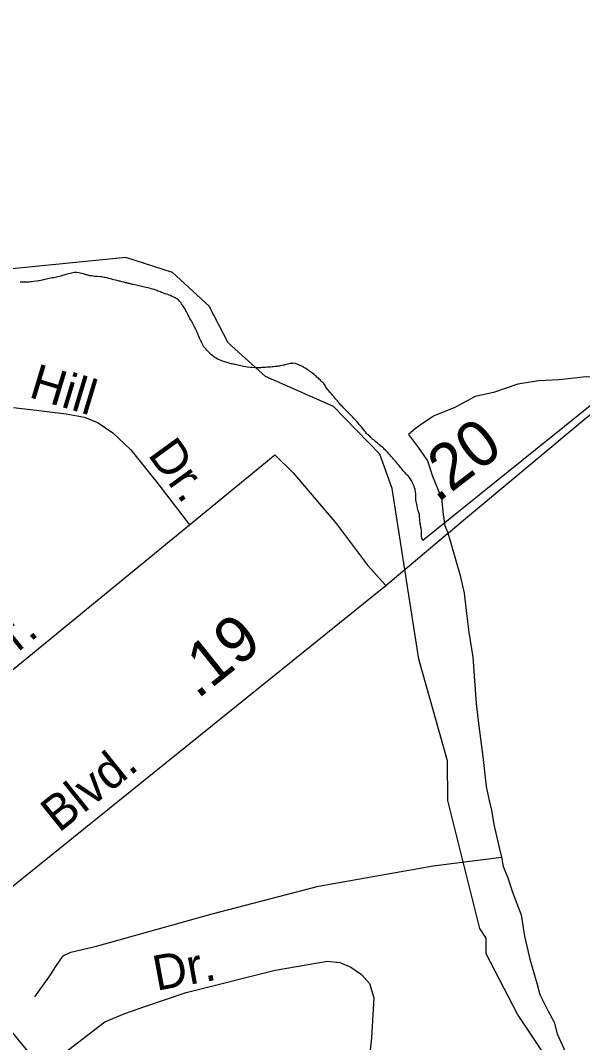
# Model space of a CAD drawing. Extents: x 2315291 to 2336543, y 597177 to 615230.
# Drawn here: x 2323766 to 2325292, y 599288 to 602063 of the extents above; entities that cross this region are included whole.
import ezdxf

# ---------------------------------------------------------------- set-up
doc = ezdxf.new("R2010")
doc.units = 0
for name, color, linetype in [('Exist Boundary Political City Limit New', 7, 'Continuous'), ('Exist Hydrographic Creek Single Shore', 7, 'Continuous'), ('Exist Hydrographic Misc Water Feature', 7, 'Continuous'), ('Exist Road Non-System Type 51', 7, 'Continuous'), ('Exist Road Non-System Type 51 Label', 7, 'Continuous'), ('Exist Road Primary US Attributed', 7, 'Continuous'), ('Exist Road Primary US Label', 7, 'Continuous'), ('Exist Road Primary US Mileage Tenths English Label', 7, 'Continuous'), ('Map Preparation Boundary City Limit Buffer Line', 7, 'Continuous')]:
    doc.layers.add(name, color=color, linetype=linetype)

msp = doc.modelspace()

# ---------------------------------------------------------------- linework, layer by layer
at = {"layer": 'Exist Boundary Political City Limit New'}
for points in [[(2324159, 601321.2), (2324156, 601322.1), (2324152.2, 601323.5), (2324148.5, 601324.9), (2324145.8, 601326.1), (2324142.2, 601327.5), (2324139.2, 601328.7), (2324135.8, 601330.1), (2324132, 601331.6), (2324128.8, 601332.7), (2324124.2, 601333.9), (2324120.5, 601335), (2324116.5, 601336.1), (2324111.2, 601337.4), (2324106.8, 601338.4), (2324103, 601339.3), (2324099, 601340.2), (2324095.5, 601341), (2324091.2, 601341.9), (2324087.2, 601342.8), (2324083.5, 601343.6), (2324080, 601344.4), (2324076, 601345.2), (2324071.8, 601346.3), (2324068.8, 601347), (2324066, 601347.7), (2324062, 601348.7), (2324058.5, 601349.5), (2324054.2, 601350.6), (2324051.2, 601351.3), (2324047.5, 601352.3), (2324041.5, 601353.8), (2324036.8, 601355), (2324034, 601355.8), (2324031, 601356.5), (2324028, 601357.2), (2324024, 601358.2), (2324019.2, 601359.4), (2324016.5, 601360.2), (2324013.5, 601361), (2324009.8, 601362), (2324006.2, 601362.9), (2324003, 601363.7), (2324000, 601364.4), (2323996, 601365.2), (2323993.2, 601365.8), (2323989.2, 601366.5), (2323986.2, 601366.8), (2323982.2, 601367.2), (2323974.2, 601367.7), (2323970.8, 601367.9), (2323966.2, 601368.5), (2323962.2, 601369), (2323958.5, 601369.6), (2323953.8, 601370.3), (2323949, 601371.4), (2323946.2, 601372.2), (2323943.2, 601373), (2323939.5, 601374.1), (2323936.5, 601375.1), (2323931.8, 601376.4), (2323928, 601377.4), (2323924, 601378.3), (2323919.2, 601379.2), (2323916.2, 601379), (2323912.2, 601378.5), (2323908.2, 601377.9), (2323904.2, 601377.2), (2323901, 601376.6), (2323896.5, 601375.4), (2323892.8, 601374.4), (2323888.8, 601373.3), (2323883.5, 601371.8), (2323879.2, 601370.6), (2323875.2, 601369.4), (2323871.5, 601368.4), (2323867, 601367.1), (2323863.8, 601366.4), (2323859.8, 601365.7), (2323856, 601364.9), (2323852, 601364.2), (2323848.5, 601363.6), (2323844, 601362.6), (2323840.2, 601361.6), (2323836.2, 601360.8), (2323831.5, 601359.6), (2323828.5, 601358.9), (2323824.5, 601358.1), (2323820.8, 601357.2), (2323816.8, 601356.4), (2323813.5, 601355.9), (2323810, 601355.3), (2323801, 601354.2), (2323796.2, 601353.6), (2323793, 601353.4), (2323789, 601353.1), (2323785, 601352.9)], [(2323785, 601352.9), (2323780.5, 601352.6), (2323777.5, 601352.5), (2323773, 601352.7), (2323769.5, 601352.6), (2323768, 601352.8), (2323765, 601353)], [(2324449.2, 601122.7), (2324444.8, 601122.2), (2324441.2, 601121.9), (2324438.2, 601121.8), (2324435.2, 601121.5), (2324431.2, 601121.2), (2324427, 601120.9), (2324424, 601120.8), (2324420.2, 601120.6), (2324417.2, 601120.4), (2324413.2, 601120.2), (2324408.2, 601120.1), (2324405.2, 601120.2), (2324393.2, 601120.9), (2324390.2, 601121.2), (2324381.2, 601122.3), (2324377.5, 601122.8), (2324372.2, 601123.4), (2324367.5, 601124.4), (2324363.8, 601125.4), (2324359.8, 601126.4), (2324355.8, 601127.6), (2324350, 601128.8), (2324347.2, 601129.4), (2324344.2, 601130.1), (2324340.5, 601130.8), (2324337.5, 601131.4), (2324334.5, 601132.2), (2324329.8, 601133.6), (2324326.8, 601134.5), (2324323, 601135.6), (2324319.5, 601136.7), (2324315.2, 601138.1), (2324311.5, 601139.3), (2324307.8, 601140.7), (2324303.5, 601142.4), (2324300.5, 601144), (2324297.2, 601146.1), (2324293.8, 601148.2), (2324290.5, 601150.4), (2324287.8, 601152.3), (2324284.5, 601155.6), (2324281.5, 601158.3), (2324279.2, 601160.4), (2324277, 601162.7), (2324274.2, 601165.6), (2324271.8, 601168.4), (2324269, 601171.3), (2324266.2, 601174.3), (2324263.2, 601178), (2324261.8, 601180.8), (2324260, 601184.4), (2324258.2, 601187.9), (2324257, 601190.7), (2324255.5, 601193.8), (2324254, 601197.1), (2324252.2, 601200.7), (2324251.2, 601203.4), (2324250, 601206.2), (2324248.2, 601209.9), (2324247, 601212.8), (2324245.2, 601217.2), (2324243.5, 601220.9), (2324242.2, 601224), (2324241, 601226.8), (2324239.2, 601230), (2324236.8, 601235.2), (2324234.8, 601238.8), (2324232.2, 601243.8), (2324230, 601247.5), (2324227.8, 601250.9), (2324226, 601254.4), (2324224.2, 601258), (2324222.8, 601260.8), (2324220.5, 601265.1), (2324218.5, 601268.6), (2324216.8, 601272.1), (2324215, 601275.2), (2324212.8, 601279.1), (2324210.8, 601282.5), (2324208.2, 601286.6), (2324205.8, 601290.7), (2324203.2, 601294.3), (2324200.8, 601297.4), (2324198.2, 601300.5), (2324194.8, 601304.3), (2324190.2, 601307.5), (2324189, 601308.7), (2324185.8, 601310), (2324182.2, 601311.9), (2324178, 601314.1), (2324175.8, 601314.9), (2324173, 601316.1), (2324169.2, 601317.5), (2324165.5, 601319), (2324162.8, 601320), (2324159, 601321.2)], [(2325664.2, 601300), (2324858.5, 600651.2), (2324857, 600654.8), (2324855.5, 600657.3), (2324855, 600661), (2324854.2, 600665.4), (2324854.5, 600668.9), (2324854.5, 600672.9), (2324854.8, 600676.9), (2324854.8, 600680.1), (2324854, 600683.8), (2324853.2, 600686.8), (2324852.8, 600689.7), (2324851.8, 600693.6), (2324851.2, 600696.5), (2324850.8, 600700.5), (2324850.5, 600704), (2324850, 600706.9), (2324849.8, 600710.4), (2324849.5, 600713.6), (2324849, 600718.4), (2324848.8, 600721.8), (2324847.5, 600726.2), (2324846.5, 600729), (2324845.5, 600732), (2324844.5, 600735.5), (2324843.8, 600739.6), (2324843.2, 600742.6), (2324842.5, 600745.6), (2324842, 600749), (2324841, 600753.4), (2324840.2, 600757.3), (2324839.5, 600761.8), (2324839.2, 600765.2), (2324839, 600769.2), (2324839, 600773.2), (2324838.8, 600778), (2324838.2, 600783.2), (2324837.8, 600787.1), (2324837, 600790.2), (2324835.8, 600794.8), (2324834.5, 600798.6), (2324832.2, 600804.2), (2324830.5, 600807.9), (2324828.8, 600811.4), (2324826.8, 600815.4), (2324823.8, 600820), (2324821.2, 600823.2), (2324818.5, 600826.6), (2324816, 600829.1), (2324813.2, 600831.9), (2324810.2, 600834.7), (2324807.2, 600837.6), (2324805.2, 600840.1), (2324803, 600843.2), (2324800.5, 600846.4), (2324797.8, 600850), (2324795.8, 600852.4), (2324793, 600855.8), (2324790.5, 600858.8), (2324787.8, 600861.9), (2324784.8, 600865.4), (2324781.8, 600868.8), (2324778.5, 600872.4), (2324776, 600875.4), (2324773.2, 600878.4), (2324771.5, 600880.6), (2324769.5, 600882.9), (2324766, 600886.8), (2324762.8, 600890.4), (2324759.8, 600893.9), (2324757.2, 600896.2), (2324754.5, 600898.8), (2324752.5, 600900.8)], [(2324461.8, 601124.1), (2324457.2, 601123.5), (2324453.2, 601123.1), (2324449.2, 601122.7)], [(2324752.5, 600900.8), (2324750.2, 600902.8), (2324746.8, 600906.1), (2324743.5, 600908.8), (2324741.2, 600910.7), (2324738, 600913.2), (2324735, 600915.7), (2324731.8, 600918.2), (2324728.8, 600920.8), (2324725.8, 600923.4), (2324722.8, 600926), (2324719.2, 600929), (2324716.8, 600931.4), (2324714, 600934.2), (2324711, 600936.9), (2324708, 600939.4), (2324705.5, 600942), (2324702.2, 600946.5), (2324700.2, 600948.7), (2324697.8, 600951.8), (2324694.5, 600955.9), (2324691.5, 600959.6), (2324689, 600962.6), (2324686.2, 600965.6), (2324683.2, 600969.2), (2324679.8, 600973.1), (2324677, 600976.1), (2324674.2, 600979.1), (2324671.2, 600982.4), (2324668.8, 600985.2), (2324666.2, 600987.9), (2324664.2, 600990.1), (2324661.5, 600992.9), (2324658.5, 600996.1), (2324654.8, 600999.7), (2324652.2, 601002.2), (2324649.5, 601005), (2324646, 601008.4), (2324643, 601011.4), (2324639.8, 601015.1), (2324635.8, 601019.2), (2324633.2, 601022.1), (2324631.2, 601024.3), (2324629, 601027), (2324626.5, 601030.1), (2324624, 601033.2), (2324621.5, 601036.1), (2324618.8, 601039.3), (2324616.2, 601042.4), (2324614.2, 601044.7), (2324612.2, 601046.9), (2324610, 601049.6), (2324606, 601054), (2324603, 601057.5), (2324600.5, 601060.5), (2324598.5, 601062.8), (2324596, 601067), (2324594.2, 601069.6), (2324592.8, 601072.2), (2324591.2, 601074.8), (2324589.2, 601077.7), (2324587, 601080), (2324584.2, 601081.9), (2324582.5, 601084.2), (2324579.5, 601087.1), (2324576, 601090.6), (2324573.8, 601092.6), (2324570.8, 601095.2), (2324568.5, 601097.2), (2324566.2, 601099.2), (2324562.8, 601102.3), (2324559.2, 601104.9), (2324557, 601106.7), (2324553.8, 601109.1), (2324550.5, 601111.4), (2324547.5, 601113.5), (2324544, 601115.9), (2324541.5, 601117.6), (2324539, 601119.2), (2324535.5, 601121.4), (2324533, 601123.1), (2324527.8, 601125.6), (2324524.8, 601126.8), (2324521.2, 601128.4), (2324516.8, 601130.4), (2324514, 601131), (2324510, 601133), (2324505.8, 601132.2), (2324502.2, 601131.7), (2324497.8, 601131.5), (2324494.5, 601130.7), (2324490.5, 601129.8), (2324486.8, 601128.8), (2324482.8, 601127.8), (2324479.5, 601127), (2324475, 601126.2), (2324471, 601125.5), (2324468, 601125), (2324465, 601124.6), (2324461.8, 601124.1)]]:
    msp.add_lwpolyline(points, dxfattribs=at)
at = {"layer": 'Exist Hydrographic Creek Single Shore'}
msp.add_lwpolyline([(2325385.4, 599067.9), (2325242.4, 599173.7), (2325115.3, 599365.4), (2325030.4, 599529.4), (2325030.4, 599572), (2325013.4, 599597.6), (2324926.5, 599945.2), (2324925.4, 600053.4), (2324847.3, 600329.2), (2324775.3, 600792.3), (2324741.3, 600886.1), (2324615.4, 601015.5), (2324431.3, 601096.7), (2324329.3, 601187.7), (2324278.3, 601287.4), (2324178.4, 601378.5), (2324052.3, 601419.4), (2323661.3, 601380.6), (2323452.3, 601444.4), (2323301.4, 601520.3), (2323108.3, 601692.9), (2322948.3, 601906.3), (2322863.2, 602047.3), (2322862.4, 602080.1)], dxfattribs=at)
at = {"layer": 'Exist Hydrographic Misc Water Feature'}
for points in [[(2326560.3, 600813.6), (2326414.1, 600842), (2326229.1, 600925.8), (2326060.4, 600999.9), (2325711.8, 601048.3), (2325569.9, 601070.9), (2325449.3, 601087.4), (2325387.4, 601091), (2325301.7, 601095.8), (2325227.9, 601087.1), (2325171.9, 601084.6), (2325115.9, 601075.9), (2325050.1, 601053.4), (2325000.3, 601042.6), (2324944.7, 601012.1), (2324889.1, 600989.6), (2324857.1, 600969.3), (2324837.5, 600954.8), (2324819.4, 600938.9)], [(2324819.4, 600938.9), (2324846.3, 600903.2), (2324870.5, 600867.5), (2324884.8, 600825.6), (2324909.2, 600766), (2324913.7, 600721.9), (2324918.3, 600692), (2324926.5, 600672.1), (2324959.9, 600556.4), (2324970.1, 600508.6), (2324977.1, 600452.8), (2324983.5, 600402.8), (2324993.9, 600335.1), (2325003.1, 600209.2), (2325010.3, 600147.3), (2325021, 600065.4), (2325029.8, 599983.4), (2325038.4, 599945.6), (2325044.4, 599919.6), (2325050.9, 599880.1), (2325065.7, 599818.2), (2325071.8, 599792.1)], [(2323804.8, 599412.7), (2323844, 599467.2), (2323863.9, 599497.4), (2323881.5, 599523.6), (2323903, 599533.7), (2323972.6, 599550.4), (2324285.9, 599637.9), (2324574.6, 599712.9), (2324886.1, 599768.2), (2325071.8, 599792.1)], [(2325071.8, 599792.1), (2325076.1, 599766.4), (2325088.4, 599738.1), (2325101.2, 599696.5), (2325125.1, 599634.9), (2325134.2, 599576.8), (2325148.7, 599515), (2325167.4, 599449.3), (2325175.6, 599419.3), (2325198.1, 599373.7), (2325214.6, 599344.1), (2325222.8, 599312), (2325245.1, 599262.4), (2325257.6, 599232.5), (2325274, 599208.6), (2325282.2, 599186.6)]]:
    msp.add_lwpolyline(points, dxfattribs=at)
at = {"layer": 'Exist Road Non-System Type 51'}
for p, q in [((2323434.4, 600047.1), (2324225.1, 600694.3)), ((2323552, 599546.7), (2323826.4, 599215.3))]:
    msp.add_line(p, q, dxfattribs=at)
for points in [[(2323746.6, 601012.2), (2323815.5, 601004.7), (2323889.9, 600995.3), (2323939.9, 600985.8), (2323976.4, 600970.9), (2324016.9, 600943.9), (2324065.6, 600897.2), (2324141.3, 600802.5), (2324225.1, 600694.3)], [(2324225.1, 600694.3), (2324456.3, 600883.7), (2324506.3, 600835), (2324623.9, 600697), (2324707.7, 600584.8), (2324757.7, 600529.3)], [(2323826.4, 599215.3), (2323995.3, 599344.4), (2324049.4, 599367.4), (2324103.5, 599386.4), (2324215.7, 599424.2), (2324457.6, 599485.1), (2324599.5, 599509.5), (2324633.3, 599505.4), (2324663.1, 599493.2), (2324691.5, 599472.9), (2324713.1, 599448.6), (2324725.3, 599409.4), (2324718.5, 599301.2), (2324713.1, 599251.1), (2324702.7, 599170.3), (2324701, 599128.4), (2324709.5, 599090.5), (2324728, 599066.5), (2324739.4, 599053.4), (2324759, 599035.4), (2324778, 599017.1)]]:
    msp.add_lwpolyline(points, dxfattribs=at)
at = {"layer": 'Exist Road Primary US Attributed'}
msp.add_lwpolyline([(2321872.6, 598168.2), (2322100.6, 598357.7), (2322368.8, 598574.3), (2322589.4, 598759.9), (2322822.5, 598950.5), (2322989.6, 599086.8), (2323103.2, 599177.4), (2323552, 599546.7), (2323723.6, 599695.4), (2324757.7, 600529.3), (2324925.6, 600670.6), (2324932.1, 600676), (2324968.9, 600707), (2325301.4, 600984), (2325554.9, 601184.8), (2325709, 601298.4), (2326037.4, 601569.3), (2326353.8, 601821.9), (2326377, 601842), (2326507.1, 601954.4)], dxfattribs=at)
at = {"layer": 'Map Preparation Boundary City Limit Buffer Line'}
for points in [[(2324159, 601321.2), (2324156, 601322.1), (2324152.2, 601323.5), (2324148.5, 601324.9), (2324145.8, 601326.1), (2324142.2, 601327.5), (2324139.2, 601328.7), (2324135.8, 601330.1), (2324132, 601331.6), (2324128.8, 601332.7), (2324124.2, 601333.9), (2324120.5, 601335), (2324116.5, 601336.1), (2324111.2, 601337.4), (2324106.8, 601338.4), (2324103, 601339.3), (2324099, 601340.2), (2324095.5, 601341), (2324091.2, 601341.9), (2324087.2, 601342.8), (2324083.5, 601343.6), (2324080, 601344.4), (2324076, 601345.2), (2324071.8, 601346.3), (2324068.8, 601347), (2324066, 601347.7), (2324062, 601348.7), (2324058.5, 601349.5), (2324054.2, 601350.6), (2324051.2, 601351.3), (2324047.5, 601352.3), (2324041.5, 601353.8), (2324036.8, 601355), (2324034, 601355.8), (2324031, 601356.5), (2324028, 601357.2), (2324024, 601358.2), (2324019.2, 601359.4), (2324016.5, 601360.2), (2324013.5, 601361), (2324009.8, 601362), (2324006.2, 601362.9), (2324003, 601363.7), (2324000, 601364.4), (2323996, 601365.2), (2323993.2, 601365.8), (2323989.2, 601366.5), (2323986.2, 601366.8), (2323982.2, 601367.2), (2323974.2, 601367.7), (2323970.8, 601367.9), (2323966.2, 601368.5), (2323962.2, 601369), (2323958.5, 601369.6), (2323953.8, 601370.3), (2323949, 601371.4), (2323946.2, 601372.2), (2323943.2, 601373), (2323939.5, 601374.1), (2323936.5, 601375.1), (2323931.8, 601376.4), (2323928, 601377.4), (2323924, 601378.3), (2323919.2, 601379.2), (2323916.2, 601379), (2323912.2, 601378.5), (2323908.2, 601377.9), (2323904.2, 601377.2), (2323901, 601376.6), (2323896.5, 601375.4), (2323892.8, 601374.4), (2323888.8, 601373.3), (2323883.5, 601371.8), (2323879.2, 601370.6), (2323875.2, 601369.4), (2323871.5, 601368.4), (2323867, 601367.1), (2323863.8, 601366.4), (2323859.8, 601365.7), (2323856, 601364.9), (2323852, 601364.2), (2323848.5, 601363.6), (2323844, 601362.6), (2323840.2, 601361.6), (2323836.2, 601360.8), (2323831.5, 601359.6), (2323828.5, 601358.9), (2323824.5, 601358.1), (2323820.8, 601357.2), (2323816.8, 601356.4), (2323813.5, 601355.9), (2323810, 601355.3), (2323801, 601354.2), (2323796.2, 601353.6), (2323793, 601353.4), (2323789, 601353.1), (2323785, 601352.9)], [(2323785, 601352.9), (2323780.5, 601352.6), (2323777.5, 601352.5), (2323773, 601352.7), (2323769.5, 601352.6), (2323768, 601352.8), (2323765, 601353)], [(2324449.2, 601122.7), (2324444.8, 601122.2), (2324441.2, 601121.9), (2324438.2, 601121.8), (2324435.2, 601121.5), (2324431.2, 601121.2), (2324427, 601120.9), (2324424, 601120.8), (2324420.2, 601120.6), (2324417.2, 601120.4), (2324413.2, 601120.2), (2324408.2, 601120.1), (2324405.2, 601120.2), (2324393.2, 601120.9), (2324390.2, 601121.2), (2324381.2, 601122.3), (2324377.5, 601122.8), (2324372.2, 601123.4), (2324367.5, 601124.4), (2324363.8, 601125.4), (2324359.8, 601126.4), (2324355.8, 601127.6), (2324350, 601128.8), (2324347.2, 601129.4), (2324344.2, 601130.1), (2324340.5, 601130.8), (2324337.5, 601131.4), (2324334.5, 601132.2), (2324329.8, 601133.6), (2324326.8, 601134.5), (2324323, 601135.6), (2324319.5, 601136.7), (2324315.2, 601138.1), (2324311.5, 601139.3), (2324307.8, 601140.7), (2324303.5, 601142.4), (2324300.5, 601144), (2324297.2, 601146.1), (2324293.8, 601148.2), (2324290.5, 601150.4), (2324287.8, 601152.3), (2324284.5, 601155.6), (2324281.5, 601158.3), (2324279.2, 601160.4), (2324277, 601162.7), (2324274.2, 601165.6), (2324271.8, 601168.4), (2324269, 601171.3), (2324266.2, 601174.3), (2324263.2, 601178), (2324261.8, 601180.8), (2324260, 601184.4), (2324258.2, 601187.9), (2324257, 601190.7), (2324255.5, 601193.8), (2324254, 601197.1), (2324252.2, 601200.7), (2324251.2, 601203.4), (2324250, 601206.2), (2324248.2, 601209.9), (2324247, 601212.8), (2324245.2, 601217.2), (2324243.5, 601220.9), (2324242.2, 601224), (2324241, 601226.8), (2324239.2, 601230), (2324236.8, 601235.2), (2324234.8, 601238.8), (2324232.2, 601243.8), (2324230, 601247.5), (2324227.8, 601250.9), (2324226, 601254.4), (2324224.2, 601258), (2324222.8, 601260.8), (2324220.5, 601265.1), (2324218.5, 601268.6), (2324216.8, 601272.1), (2324215, 601275.2), (2324212.8, 601279.1), (2324210.8, 601282.5), (2324208.2, 601286.6), (2324205.8, 601290.7), (2324203.2, 601294.3), (2324200.8, 601297.4), (2324198.2, 601300.5), (2324194.8, 601304.3), (2324190.2, 601307.5), (2324189, 601308.7), (2324185.8, 601310), (2324182.2, 601311.9), (2324178, 601314.1), (2324175.8, 601314.9), (2324173, 601316.1), (2324169.2, 601317.5), (2324165.5, 601319), (2324162.8, 601320), (2324159, 601321.2)], [(2325664.2, 601300), (2324858.5, 600651.2), (2324857, 600654.8), (2324855.5, 600657.3), (2324855, 600661), (2324854.2, 600665.4), (2324854.5, 600668.9), (2324854.5, 600672.9), (2324854.8, 600676.9), (2324854.8, 600680.1), (2324854, 600683.8), (2324853.2, 600686.8), (2324852.8, 600689.7), (2324851.8, 600693.6), (2324851.2, 600696.5), (2324850.8, 600700.5), (2324850.5, 600704), (2324850, 600706.9), (2324849.8, 600710.4), (2324849.5, 600713.6), (2324849, 600718.4), (2324848.8, 600721.8), (2324847.5, 600726.2), (2324846.5, 600729), (2324845.5, 600732), (2324844.5, 600735.5), (2324843.8, 600739.6), (2324843.2, 600742.6), (2324842.5, 600745.6), (2324842, 600749), (2324841, 600753.4), (2324840.2, 600757.3), (2324839.5, 600761.8), (2324839.2, 600765.2), (2324839, 600769.2), (2324839, 600773.2), (2324838.8, 600778), (2324838.2, 600783.2), (2324837.8, 600787.1), (2324837, 600790.2), (2324835.8, 600794.8), (2324834.5, 600798.6), (2324832.2, 600804.2), (2324830.5, 600807.9), (2324828.8, 600811.4), (2324826.8, 600815.4), (2324823.8, 600820), (2324821.2, 600823.2), (2324818.5, 600826.6), (2324816, 600829.1), (2324813.2, 600831.9), (2324810.2, 600834.7), (2324807.2, 600837.6), (2324805.2, 600840.1), (2324803, 600843.2), (2324800.5, 600846.4), (2324797.8, 600850), (2324795.8, 600852.4), (2324793, 600855.8), (2324790.5, 600858.8), (2324787.8, 600861.9), (2324784.8, 600865.4), (2324781.8, 600868.8), (2324778.5, 600872.4), (2324776, 600875.4), (2324773.2, 600878.4), (2324771.5, 600880.6), (2324769.5, 600882.9), (2324766, 600886.8), (2324762.8, 600890.4), (2324759.8, 600893.9), (2324757.2, 600896.2), (2324754.5, 600898.8), (2324752.5, 600900.8)], [(2324461.8, 601124.1), (2324457.2, 601123.5), (2324453.2, 601123.1), (2324449.2, 601122.7)], [(2324752.5, 600900.8), (2324750.2, 600902.8), (2324746.8, 600906.1), (2324743.5, 600908.8), (2324741.2, 600910.7), (2324738, 600913.2), (2324735, 600915.7), (2324731.8, 600918.2), (2324728.8, 600920.8), (2324725.8, 600923.4), (2324722.8, 600926), (2324719.2, 600929), (2324716.8, 600931.4), (2324714, 600934.2), (2324711, 600936.9), (2324708, 600939.4), (2324705.5, 600942), (2324702.2, 600946.5), (2324700.2, 600948.7), (2324697.8, 600951.8), (2324694.5, 600955.9), (2324691.5, 600959.6), (2324689, 600962.6), (2324686.2, 600965.6), (2324683.2, 600969.2), (2324679.8, 600973.1), (2324677, 600976.1), (2324674.2, 600979.1), (2324671.2, 600982.4), (2324668.8, 600985.2), (2324666.2, 600987.9), (2324664.2, 600990.1), (2324661.5, 600992.9), (2324658.5, 600996.1), (2324654.8, 600999.7), (2324652.2, 601002.2), (2324649.5, 601005), (2324646, 601008.4), (2324643, 601011.4), (2324639.8, 601015.1), (2324635.8, 601019.2), (2324633.2, 601022.1), (2324631.2, 601024.3), (2324629, 601027), (2324626.5, 601030.1), (2324624, 601033.2), (2324621.5, 601036.1), (2324618.8, 601039.3), (2324616.2, 601042.4), (2324614.2, 601044.7), (2324612.2, 601046.9), (2324610, 601049.6), (2324606, 601054), (2324603, 601057.5), (2324600.5, 601060.5), (2324598.5, 601062.8), (2324596, 601067), (2324594.2, 601069.6), (2324592.8, 601072.2), (2324591.2, 601074.8), (2324589.2, 601077.7), (2324587, 601080), (2324584.2, 601081.9), (2324582.5, 601084.2), (2324579.5, 601087.1), (2324576, 601090.6), (2324573.8, 601092.6), (2324570.8, 601095.2), (2324568.5, 601097.2), (2324566.2, 601099.2), (2324562.8, 601102.3), (2324559.2, 601104.9), (2324557, 601106.7), (2324553.8, 601109.1), (2324550.5, 601111.4), (2324547.5, 601113.5), (2324544, 601115.9), (2324541.5, 601117.6), (2324539, 601119.2), (2324535.5, 601121.4), (2324533, 601123.1), (2324527.8, 601125.6), (2324524.8, 601126.8), (2324521.2, 601128.4), (2324516.8, 601130.4), (2324514, 601131), (2324510, 601133), (2324505.8, 601132.2), (2324502.2, 601131.7), (2324497.8, 601131.5), (2324494.5, 601130.7), (2324490.5, 601129.8), (2324486.8, 601128.8), (2324482.8, 601127.8), (2324479.5, 601127), (2324475, 601126.2), (2324471, 601125.5), (2324468, 601125), (2324465, 601124.6), (2324461.8, 601124.1)]]:
    msp.add_lwpolyline(points, dxfattribs=at)

# ---------------------------------------------------------------- texts
at = {"layer": 'Exist Road Non-System Type 51 Label'}
for s, rotation, p in [('Hill', 343.2338, (2323785.5, 601041.6)), ('Dr.', 305.9838, (2324109.7, 600884.3)), ('Dr.', 39.4242, (2323688.5, 600289.2)), ('Dr.', 10.5013, (2324135.1, 599428.6))]:
    msp.add_text(s, height=95, rotation=rotation, dxfattribs=at).set_placement(p)
at = {"layer": 'Exist Road Primary US Label'}
msp.add_text('Blvd.', height=95, rotation=38.6909, dxfattribs=at).set_placement((2323870.5, 599856.5))
at = {"layer": 'Exist Road Primary US Mileage Tenths English Label'}
for s, rotation, p in [('.20', 37.5195, (2324897.2, 600751.6)), ('.19', 38.6909, (2324246.3, 600218.9))]:
    msp.add_text(s, height=125, rotation=rotation, dxfattribs=at).set_placement(p)

doc.saveas('drawing.dxf')
